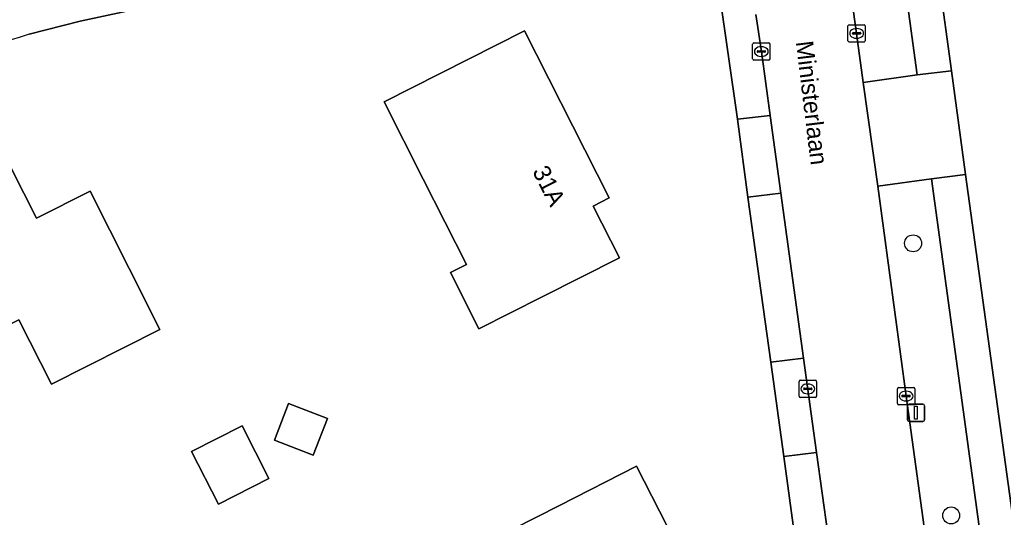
# Model space of a CAD drawing. Extents: x 162722 to 165104, y 384719 to 386284.
# Drawn here: x 164060.8 to 164117.6, y 385053.7 to 385082.4 of the extents above; entities that cross this region are included whole.
import ezdxf

# ---------------------------------------------------------------- set-up
doc = ezdxf.new("R2010")
doc.units = 0
for name, color, linetype in [('IMGEO_Boom', 7, 'Continuous'), ('IMGEO_Erf', 7, 'Continuous'), ('IMGEO_Groenvoorziening', 7, 'Continuous'), ('IMGEO_Kolk', 7, 'Continuous'), ('IMGEO_Lichtmast', 7, 'Continuous'), ('IMGEO_Openbare_ruimte_label', 7, 'Continuous'), ('IMGEO_Pand', 7, 'Continuous'), ('IMGEO_Pand_nummerreeks', 7, 'Continuous'), ('IMGEO_Parkeervlak_open', 7, 'Continuous'), ('IMGEO_Rijbaan_lokaal_open', 7, 'Continuous'), ('IMGEO_Voetpad_open', 7, 'Continuous')]:
    doc.layers.add(name, color=color, linetype=linetype)

msp = doc.modelspace()

# ---------------------------------------------------------------- linework, layer by layer
at = {"layer": 'IMGEO_Boom'}
for centre in [(164112.357, 385069.518), (164114.559, 385053.8)]:
    msp.add_circle(centre, 0.489, dxfattribs=at)
at = {"layer": 'IMGEO_Erf'}
for points in [[(164163.257, 385048.667), (164153.955, 385115.885), (164147.888, 385159.149), (164138.564, 385158), (164106.097, 385141.08), (164107.204, 385132.889), (164107.861, 385128.069), (164109.929, 385113.435), (164111.013, 385105.498), (164114.568, 385079.483), (164115.377, 385073.493), (164118.85, 385048.373)], [(164096.697, 385087.125), (164067.493, 385083.035), (164064.259, 385082.346), (164061.303, 385081.589)], [(164104.891, 385057.208), (164104.135, 385062.651), (164102.823, 385072.185), (164102.21, 385076.684), (164101.164, 385084.076)], [(164106.536, 385045.173), (164104.891, 385057.208)]]:
    msp.add_lwpolyline(points, dxfattribs=at)
for points in [[(164084.059, 385073.231), (164081.801, 385077.692), (164089.915, 385081.799), (164094.806, 385072.136), (164093.882, 385071.669), (164095.394, 385068.68), (164090.933, 385066.422), (164087.283, 385064.575), (164085.64, 385067.823), (164086.56, 385068.288)], [(164053.405, 385061.402), (164055.285, 385057.684), (164049.027, 385054.522), (164047.243, 385058.053), (164044.989, 385062.515), (164048.074, 385064.074), (164045.875, 385068.428), (164052.7, 385071.87), (164059.525, 385075.312), (164061.721, 385070.968), (164064.824, 385072.535), (164067.079, 385068.073), (164068.862, 385064.543), (164062.596, 385061.377), (164060.717, 385065.097), (164057.048, 385063.243)], [(164075.47, 385058.146), (164076.292, 385060.263), (164078.535, 385059.391), (164077.713, 385057.274)], [(164070.691, 385057.492), (164073.602, 385058.97), (164075.144, 385055.934), (164072.233, 385054.455)], [(164086.555, 385051.648), (164091.931, 385054.383), (164096.387, 385056.649), (164099.494, 385050.541), (164096.118, 385048.824), (164097.107, 385046.88), (164097.581, 385047.121), (164100.028, 385042.31), (164099.622, 385042.103), (164100.224, 385040.92), (164092.225, 385036.851), (164089.958, 385041.308), (164087.45, 385046.24), (164088.924, 385046.99)]]:
    msp.add_lwpolyline(points, close=True, dxfattribs=at)
msp.add_arc((164085.418, 385002.08), 83.086, 106.87221, 112.85582, dxfattribs=at)
at = {"layer": 'IMGEO_Groenvoorziening'}
msp.add_lwpolyline([(164112.597, 385079.241), (164109.746, 385100.117), (164106.583, 385099.714), (164109.099, 385081.644), (164109.468, 385078.814)], close=True, dxfattribs=at)
msp.add_lwpolyline([(164117.043, 385046.479), (164116.295, 385052.312), (164113.428, 385073.243), (164110.323, 385072.813), (164111.956, 385060.695), (164113.896, 385046.54), (164114.074, 385044.319), (164114.117, 385043.575), (164114.097, 385042.613), (164113.99, 385041.657), (164113.799, 385040.714), (164116.814, 385040.352)], dxfattribs=at)
at = {"layer": 'IMGEO_Kolk'}
for p, q in [((164108.598, 385081.218), (164108.598, 385082.07)), ((164108.673, 385082.144), (164109.525, 385082.144)), ((164109.086, 385081.924), (164109.111, 385081.924)), ((164109.599, 385082.07), (164109.599, 385081.218)), ((164109.525, 385081.144), (164108.673, 385081.144)), ((164108.857, 385081.638), (164108.857, 385081.65)), ((164109.295, 385081.601), (164108.897, 385081.601)), ((164108.9, 385081.687), (164109.298, 385081.687)), ((164109.109, 385081.364), (164109.084, 385081.364)), ((164109.341, 385081.65), (164109.341, 385081.638)), ((164103.093, 385080.169), (164103.093, 385081.021)), ((164103.168, 385081.095), (164104.02, 385081.095)), ((164103.352, 385080.589), (164103.352, 385080.601)), ((164103.395, 385080.638), (164103.793, 385080.638)), ((164103.581, 385080.875), (164103.606, 385080.875)), ((164103.836, 385080.601), (164103.836, 385080.589)), ((164104.094, 385081.021), (164104.094, 385080.169)), ((164104.02, 385080.095), (164103.168, 385080.095)), ((164103.79, 385080.552), (164103.392, 385080.552)), ((164103.604, 385080.315), (164103.579, 385080.315)), ((164105.778, 385060.686), (164105.778, 385061.538)), ((164105.853, 385061.612), (164106.705, 385061.612)), ((164106.266, 385061.392), (164106.291, 385061.392)), ((164106.779, 385061.538), (164106.779, 385060.686)), ((164106.037, 385061.106), (164106.037, 385061.118)), ((164106.475, 385061.069), (164106.077, 385061.069)), ((164106.08, 385061.155), (164106.478, 385061.155)), ((164106.289, 385060.832), (164106.264, 385060.832)), ((164106.521, 385061.118), (164106.521, 385061.106)), ((164111.455, 385060.269), (164111.455, 385061.121)), ((164111.53, 385061.195), (164112.382, 385061.195)), ((164111.714, 385060.689), (164111.714, 385060.701)), ((164111.757, 385060.738), (164112.155, 385060.738)), ((164111.943, 385060.975), (164111.968, 385060.975)), ((164112.198, 385060.701), (164112.198, 385060.689)), ((164112.456, 385061.121), (164112.456, 385060.269)), ((164106.705, 385060.612), (164105.853, 385060.612)), ((164112.382, 385060.195), (164111.53, 385060.195)), ((164112.152, 385060.652), (164111.754, 385060.652)), ((164111.966, 385060.415), (164111.941, 385060.415))]:
    msp.add_line(p, q, dxfattribs=at)
for points in [[(164108.598, 385081.218), (164108.598, 385082.07)], [(164108.673, 385082.144), (164109.525, 385082.144)], [(164109.599, 385082.07), (164109.599, 385081.218)], [(164109.525, 385081.144), (164108.673, 385081.144)], [(164103.093, 385080.169), (164103.093, 385081.021)], [(164103.168, 385081.095), (164104.02, 385081.095)], [(164104.094, 385081.021), (164104.094, 385080.169)], [(164104.02, 385080.095), (164103.168, 385080.095)], [(164105.778, 385060.686), (164105.778, 385061.538)], [(164105.853, 385061.612), (164106.705, 385061.612)], [(164106.779, 385061.538), (164106.779, 385060.686)], [(164111.455, 385060.269), (164111.455, 385061.121)], [(164111.53, 385061.195), (164112.382, 385061.195)], [(164112.456, 385061.121), (164112.456, 385060.269)], [(164106.705, 385060.612), (164105.853, 385060.612)], [(164112.382, 385060.195), (164111.53, 385060.195)]]:
    msp.add_lwpolyline(points, dxfattribs=at)
for centre, radius, start, end in [((164108.675, 385082.068), 0.0765, 91.552, 178.448), ((164108.675, 385082.068), 0.0765, 91.552, 178.448), ((164109.523, 385082.068), 0.0765, 1.552, 88.448), ((164109.523, 385082.068), 0.0765, 1.552, 88.448), ((164108.675, 385081.22), 0.0765, 181.552, 268.448), ((164108.675, 385081.22), 0.0765, 181.552, 268.448), ((164108.897, 385081.647), 0.0403, 85.8775, 175.7526), ((164108.894, 385081.637), 0.0366, 178.938, 274.7102), ((164109.298, 385081.644), 0.043, 264.8664, 352.4533), ((164109.302, 385081.649), 0.0386, 1.7309, 96.639), ((164109.523, 385081.22), 0.0765, 271.552, 358.448), ((164109.523, 385081.22), 0.0765, 271.552, 358.448), ((164103.17, 385081.019), 0.0765, 91.552, 178.448), ((164103.17, 385081.019), 0.0765, 91.552, 178.448), ((164103.392, 385080.598), 0.0403, 85.8775, 175.7526), ((164103.389, 385080.588), 0.0366, 178.938, 274.7102), ((164103.793, 385080.595), 0.043, 264.8664, 352.4533), ((164103.797, 385080.6), 0.0386, 1.7309, 96.639), ((164104.018, 385081.019), 0.0765, 1.552, 88.448), ((164104.018, 385081.019), 0.0765, 1.552, 88.448), ((164103.17, 385080.171), 0.0765, 181.552, 268.448), ((164103.17, 385080.171), 0.0765, 181.552, 268.448), ((164104.018, 385080.171), 0.0765, 271.552, 358.448), ((164104.018, 385080.171), 0.0765, 271.552, 358.448), ((164105.855, 385061.536), 0.0765, 91.552, 178.448), ((164105.855, 385061.536), 0.0765, 91.552, 178.448), ((164106.703, 385061.536), 0.0765, 1.552, 88.448), ((164106.703, 385061.536), 0.0765, 1.552, 88.448), ((164106.077, 385061.115), 0.0403, 85.8775, 175.7526), ((164106.074, 385061.105), 0.0366, 178.938, 274.7102), ((164106.478, 385061.112), 0.043, 264.8664, 352.4533), ((164106.482, 385061.117), 0.0386, 1.7309, 96.639), ((164111.532, 385061.119), 0.0765, 91.552, 178.448), ((164111.532, 385061.119), 0.0765, 91.552, 178.448), ((164111.754, 385060.698), 0.0403, 85.8775, 175.7526), ((164112.159, 385060.7), 0.0386, 1.7309, 96.639), ((164112.38, 385061.119), 0.0765, 1.552, 88.448), ((164112.38, 385061.119), 0.0765, 1.552, 88.448), ((164105.855, 385060.688), 0.0765, 181.552, 268.448), ((164105.855, 385060.688), 0.0765, 181.552, 268.448), ((164106.703, 385060.688), 0.0765, 271.552, 358.448), ((164106.703, 385060.688), 0.0765, 271.552, 358.448), ((164111.532, 385060.271), 0.0765, 181.552, 268.448), ((164111.532, 385060.271), 0.0765, 181.552, 268.448), ((164111.751, 385060.688), 0.0366, 178.938, 274.7102), ((164112.155, 385060.695), 0.043, 264.8664, 352.4533), ((164112.38, 385060.271), 0.0765, 271.552, 358.448), ((164112.38, 385060.271), 0.0765, 271.552, 358.448)]:
    msp.add_arc(centre, radius, start, end, dxfattribs=at)
for centre, major_axis, ratio, start_param, end_param in [((164109.085, 385081.644), (-0.387, 0.002), 0.722429, 4.712389, 7.853982), ((164109.11, 385081.644), (-0.39, 0.002), 0.717154, 1.570796, 4.712389), ((164103.58, 385080.595), (-0.387, 0.002), 0.722429, 4.712389, 7.853982), ((164103.605, 385080.595), (-0.39, 0.002), 0.717154, 1.570796, 4.712389), ((164106.265, 385061.112), (-0.387, 0.002), 0.722429, 4.712389, 7.853982), ((164106.29, 385061.112), (-0.39, 0.002), 0.717154, 1.570796, 4.712389), ((164111.942, 385060.695), (-0.387, 0.002), 0.722429, 4.712389, 7.853982), ((164111.967, 385060.695), (-0.39, 0.002), 0.717154, 1.570796, 4.712389)]:
    msp.add_ellipse(centre, major_axis=major_axis, ratio=ratio, start_param=start_param, end_param=end_param, dxfattribs=at)
at = {"layer": 'IMGEO_Lichtmast'}
for p, q in [((164112.029, 385059.329), (164112.029, 385060.129)), ((164112.029, 385060.129), (164112.029, 385059.329)), ((164112.129, 385060.229), (164112.919, 385060.229)), ((164112.919, 385060.229), (164112.129, 385060.229)), ((164113.019, 385060.129), (164113.019, 385059.329)), ((164113.019, 385059.329), (164113.019, 385060.129)), ((164112.919, 385059.229), (164112.129, 385059.229)), ((164112.129, 385059.229), (164112.919, 385059.229))]:
    msp.add_line(p, q, dxfattribs=at)
msp.add_lwpolyline([(164112.449, 385060.104), (164112.599, 385060.104), (164112.599, 385059.354), (164112.449, 385059.354), (164112.449, 385060.104)], dxfattribs=at)
for centre, start, end in [((164112.129, 385060.129), 90, 180), ((164112.129, 385060.129), 90, 180), ((164112.919, 385060.129), 0, 90), ((164112.919, 385060.129), 360, 90), ((164112.129, 385059.329), 180, 270), ((164112.129, 385059.329), 180, 270), ((164112.919, 385059.329), 270, 0), ((164112.919, 385059.329), 270, 0)]:
    msp.add_arc(centre, 0.1, start, end, dxfattribs=at)
at = {"layer": 'IMGEO_Pand'}
for points in [[(164084.059, 385073.231), (164086.56, 385068.288), (164085.64, 385067.823), (164087.283, 385064.575), (164090.933, 385066.422), (164095.394, 385068.68), (164093.882, 385071.669), (164094.806, 385072.136), (164089.915, 385081.799), (164081.801, 385077.692)], [(164057.048, 385063.243), (164060.717, 385065.097), (164062.596, 385061.377), (164068.862, 385064.543), (164067.079, 385068.073), (164064.824, 385072.535), (164061.721, 385070.968), (164059.525, 385075.312), (164052.7, 385071.87)], [(164075.47, 385058.146), (164077.713, 385057.274), (164078.535, 385059.391), (164076.292, 385060.263)], [(164070.691, 385057.492), (164072.233, 385054.455), (164075.144, 385055.934), (164073.602, 385058.97)], [(164092.225, 385036.851), (164100.224, 385040.92), (164099.622, 385042.103), (164100.028, 385042.31), (164097.581, 385047.121), (164097.107, 385046.88), (164096.118, 385048.824), (164099.494, 385050.541), (164096.387, 385056.649), (164091.931, 385054.383), (164086.555, 385051.648), (164088.924, 385046.99), (164087.45, 385046.24), (164089.958, 385041.308)]]:
    msp.add_lwpolyline(points, close=True, dxfattribs=at)
at = {"layer": 'IMGEO_Parkeervlak_open'}
msp.add_lwpolyline([(164104.718, 385072.421), (164102.823, 385072.185), (164104.135, 385062.651), (164106.033, 385062.888)], close=True, dxfattribs=at)
msp.add_lwpolyline([(164108.436, 385045.432), (164108.425, 385045.686), (164106.788, 385057.445), (164104.891, 385057.208), (164106.536, 385045.173)], dxfattribs=at)
at = {"layer": 'IMGEO_Rijbaan_lokaal_open'}
for points in [[(164103.283, 385082.726), (164103.594, 385080.595), (164104.101, 385076.908), (164104.718, 385072.421), (164106.033, 385062.888), (164106.788, 385057.445), (164108.425, 385045.686), (164108.436, 385045.432), (164113.799, 385040.714), (164113.99, 385041.657), (164114.097, 385042.613), (164114.117, 385043.575), (164114.074, 385044.319), (164113.896, 385046.54), (164111.956, 385060.695), (164110.323, 385072.813), (164109.468, 385078.814), (164109.099, 385081.644), (164106.583, 385099.714)], [(164061.303, 385081.589), (164064.259, 385082.346), (164067.493, 385083.035), (164096.697, 385087.125)]]:
    msp.add_lwpolyline(points, dxfattribs=at)
msp.add_arc((164085.418, 385002.08), 83.086, 106.87221, 112.85582, dxfattribs=at)
at = {"layer": 'IMGEO_Voetpad_open'}
for points in [[(164112.597, 385079.241), (164114.568, 385079.483), (164111.013, 385105.498), (164109.069, 385105.197), (164109.418, 385102.686), (164106.23, 385102.25), (164106.583, 385099.714), (164109.746, 385100.117)], [(164113.428, 385073.243), (164115.377, 385073.493), (164114.568, 385079.483), (164112.597, 385079.241), (164109.468, 385078.814), (164110.323, 385072.813)], [(164104.101, 385076.908), (164102.21, 385076.684), (164102.823, 385072.185), (164104.718, 385072.421)], [(164106.033, 385062.888), (164104.135, 385062.651), (164104.891, 385057.208), (164106.788, 385057.445)]]:
    msp.add_lwpolyline(points, close=True, dxfattribs=at)
for points in [[(164101.164, 385084.076), (164102.21, 385076.684), (164104.101, 385076.908), (164103.594, 385080.595), (164103.283, 385082.726)], [(164118.85, 385048.373), (164115.377, 385073.493), (164113.428, 385073.243), (164116.295, 385052.312), (164117.043, 385046.479)]]:
    msp.add_lwpolyline(points, dxfattribs=at)

# ---------------------------------------------------------------- texts
at = {"layer": 'IMGEO_Openbare_ruimte_label'}
msp.add_text('Ministerlaan', height=1, rotation=276.9474, dxfattribs=at).set_placement((164105.584, 385081.153))
at = {"layer": 'IMGEO_Pand_nummerreeks'}
msp.add_text('31A', height=1, rotation=296.8466, dxfattribs=at).set_placement((164090.349, 385073.681))

doc.saveas('drawing.dxf')
